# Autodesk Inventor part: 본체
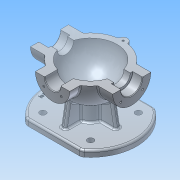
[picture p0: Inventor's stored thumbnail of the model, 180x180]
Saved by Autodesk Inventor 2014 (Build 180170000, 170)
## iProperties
Created: 2015-12
Part Number: 본체
Material: 알루미늄 6061
Document SubType Name: Modeling
Designer: mduedu
Density: 2.71 g/cm^3
Mass: 1035.31 g
Surface Area: 843.851 cm^2
Volume: 382.033 cm^3
Appearance: 알루미늄 - 평지
Author: mduedu
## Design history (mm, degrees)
sketch "스케치1"
  geometry: L1 (-53, 0)-(53, 0); A1 r 53 centre (0, 0) between (53, 0) and (-53, 0); 2 further points
  constraints: 2 coincident, 2 end point, 2 point on circle, 1 centre point, 1 horizontal, 1 midpoint
  dimensions: "d0" = 53 radius of A1
revolve "회전1" sketch "스케치1" stored, may be unused: angle "d2" = 90 deg
feature "쉘1" dims "d11" = 10
node "작업 평면1"
sketch "스케치2"
  geometry: C1 r 31 at (0, 0); 1 further point
  constraints: 1 centre point, 1 coincident
  dimensions: "d4" = 62 diameter of C1
extrude "돌출1" join sketch "스케치2" stored distance "d5" = 10; taper "d6" = 0 deg
node "작업 평면2"
sketch "스케치3"
  geometry: C1 r 28 at (0, 0); 1 further point
  constraints: 1 centre point, 1 coincident
  dimensions: "d8" = 56 diameter of C1
extrude "돌출2" join sketch "스케치3" stored distance "d9" = 10; taper "d10" = 0 deg
hole "구멍1" diameter "d14" = 35; stored, may be unused: countersink angle "d18" = 90 deg, drill point angle "d20" = 0 deg; dims "d12" = 10, "d13" = 10, "d15" = 6, "d16" = 4, "d17" = 2, "d19" = 16
hole "구멍2" diameter "d23" = 27; stored, may be unused: countersink angle "d27" = 90 deg, drill point angle "d29" = 0 deg; dims "d21" = 10, "d22" = 10, "d24" = 6, "d25" = 4, "d26" = 2, "d28" = 16
fillet "모깎기1" dims "d30" = 0.3
hole "구멍3" diameter "d33" = 26; stored, may be unused: countersink angle "d37" = 90 deg, drill point angle "d39" = 0 deg; dims "d31" = 10, "d32" = 10, "d34" = 6, "d35" = 4, "d36" = 2, "d38" = 16
chamfer "모따기1" distance "d40" = 1; stored, may be unused: second distance "d41" = 2, angle "d42" = 45 deg
sketch "스케치4"
  geometry: L1 (0, 0)-(0, -25); L2 (0, 0)-(-17.678, -17.678); A1 r 25 centre (0, 0) between (-17.678, -17.678) and (0, -25); 1 further point
  constraints: 4 end point, 2 point on circle, 1 centre point, 1 coincident, 1 vertical
  dimensions: "d43" = 50 diameter of A1; "d47" = 45 deg angle of L1 L2
hole "구멍4" sketch "스케치4" at (-17.678, -17.678) diameter "d49" = 3.242; stored, may be unused: countersink angle "d53" = 90 deg, drill point angle "d55" = 118 deg; dims "d50" = 11, "d51" = 4, "d52" = 2, "d54" = 13
sketch "스케치5"
  geometry: L1 (0, 0)-(0, -20); L2 (0, 0)-(-14.142, -14.142); A1 r 20 centre (0, 0) between (0, -20) and (-14.142, -14.142); 2 further points
  constraints: 4 end point, 2 coincident, 2 point on circle, 1 centre point, 1 vertical
  dimensions: "d59" = 40 diameter of A1; "d65" = 45 deg angle of L1 L2
hole "구멍5" sketch "스케치5" at (-14.142, -14.142) diameter "d67" = 3.242; stored, may be unused: countersink angle "d71" = 90 deg, drill point angle "d73" = 118 deg; dims "d68" = 8, "d69" = 4, "d70" = 2, "d72" = 10
node "작업 평면3"
sketch "스케치6"
  geometry: C1 r 75 at (0, 0); 1 further point
  constraints: 1 centre point, 1 coincident
  dimensions: "d78" = 150 diameter of C1
extrude "돌출3" join sketch "스케치6" distance "d80" = 10; taper "d81" = 0 deg
sketch "스케치7"
  geometry: C1 r 20 at (0, 0); 1 further point
  constraints: 1 centre point, 1 coincident
  dimensions: "d82" = 40 diameter of C1
extrude "돌출4" join sketch "스케치7" stored distance "d84" = 10; taper "d85" = 0 deg
sketch "스케치8"
  geometry: 2 further points
  constraints: 1 coincident
hole "구멍6" sketch "스케치8" at (0, 0) diameter "d86" = 20; stored, may be unused: countersink angle "d90" = 90 deg, drill point angle "d92" = 118 deg; dims "d87" = 7, "d88" = 40, "d89" = 5, "d91" = 10
fillet "모깎기2" dims "d93" = 0.3
sketch "스케치9"
  geometry: L1 (75, -75)-(-75, -75) reference; L2 (-45, -75)-(-38.245, -36.692); A1 r 53 centre (0, 0) between (42.988, 31) and (42.988, -31) reference; 1 further point
  constraints: 2 end point, 1 point on circle, 1 point on line
  dimensions: "d94" = 45 horizontal distance of L2.start point (0, 0); "d95" = 80 deg angle of L2 L1
feature "리브1" sketch "스케치9" dims "d96" = 1, "d97" = 8, "d98" = 0, "d99" = 0, "d100" = 1, "d101" = 1
sketch "스케치14"
  geometry: L1 (-45, 110)-(45, 110); L2 (45, 110)-(45, 60); L3 (45, 60)-(-45, 60); L4 (-45, 60)-(-45, 110); L5 (-45, 110)-(45, 60); L6 (45, 110)-(-45, 60); L7 (-75, 0)-(75, 0); L8 (-45, -110)-(45, -110); L9 (45, -110)-(45, -60); L10 (45, -60)-(-45, -60); L11 (-45, -60)-(-45, -110); L12 (-45, -110)-(45, -60); L13 (45, -110)-(-45, -60); A1 r 75 centre (0, 0) between (45, 60) and (-45, 60) reference; 4 further points
  constraints: 26 end point, 5 midpoint, 5 symmetric about line, 4 point on circle, 2 parallel, 2 perpendicular, 1 coincident, 1 horizontal
  dimensions: "d151" = 15 distance edge to line of A1 L3; "d152" = 50 distance of L3.end L1.start
extrude "돌출7" cut sketch "스케치14" stored distance "d153" = 0; taper "d154" = 0 deg
fillet "모깎기9" dims "d155" = 10
sketch "스케치10"
  geometry: L1 (0, 0)-(0, -55); L2 (0, 0)-(-38.891, -38.891); A1 r 55 centre (0, 0) between (0, -55) and (-38.891, -38.891); 2 further points
  constraints: 4 end point, 2 coincident, 2 point on circle, 1 centre point, 1 vertical
  dimensions: "d105" = 110 diameter of A1; "d107" = 45 deg angle of L1 L2
hole "구멍7" sketch "스케치10" at (-38.891, -38.891) diameter "d109" = 10; stored, may be unused: countersink angle "d113" = 90 deg, drill point angle "d115" = 118 deg; dims "d110" = 7, "d111" = 40, "d112" = 5, "d114" = 10
fillet "모깎기3" dims "d120" = 3
fillet "모깎기4" dims "d121" = 3, "d122" = 3
fillet "모깎기5" dims "d123" = 3
fillet "모깎기6" dims "d124" = 3
sketch "스케치11"
  geometry: 2 further points
  constraints: 1 vertical alignment, 1 other
  dimensions: "d157" = 63 distance of point (0, 63) point (0, 0)
feature "엠보싱1" sketch "스케치11" dims "d125" = 0.5, "d126" = 0
sketch "스케치12"
  geometry: L1 (0, 100)-(0, -100); L2 (0, 100)-(100, 100); L3 (100, 100)-(100, -100); L4 (100, -100)-(0, -100); 2 further points
  constraints: 8 end point, 3 perpendicular, 1 coincident, 1 midpoint, 1 vertical
  dimensions: "d127" = 200 distance of L2.end L3.end; "d129" = 100 distance between parallel lines of L1 L3
extrude "돌출5" cut sketch "스케치12" stored distance "d130" = 10; taper "d131" = 0 deg
sketch "스케치13"
  geometry: C1 r 7 at (0, 53); A1 r 53 centre (0, 0) between (42.113, 32.179) and (-42.113, 32.179) reference; 1 further point
  constraints: 1 centre point, 1 point on circle
  dimensions: "d132" = 14 diameter of C1
extrude "돌출6" join sketch "스케치13" distance "d134" = 15; taper "d135" = 0 deg; dims "d29" = 0
hole "구멍8" diameter "d139" = 3.242; stored, may be unused: countersink angle "d143" = 90 deg, drill point angle "d145" = 118 deg; dims "d140" = 8, "d141" = 4, "d142" = 2, "d144" = 10, "d148" = 10, "d149" = 10
fillet "모깎기7" dims "d146" = 3
fillet "모깎기8" dims "d147" = 3
node "솔리드1"
mirror "대칭1"
mirror "대칭2"
pattern_circular "원형 패턴1" dims angle "d57" = 360 deg
mirror "대칭3"
pattern_circular "원형 패턴2" dims angle "d75" = 360 deg
pattern_circular "원형 패턴3" dims angle "d103" = 360 deg
pattern_circular "원형 패턴4" dims angle "d118" = 360 deg
other parameters: "d3" = 67, "d7" = 62, "d77" = -85
